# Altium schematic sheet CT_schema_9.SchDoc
size 278 x 170 mm
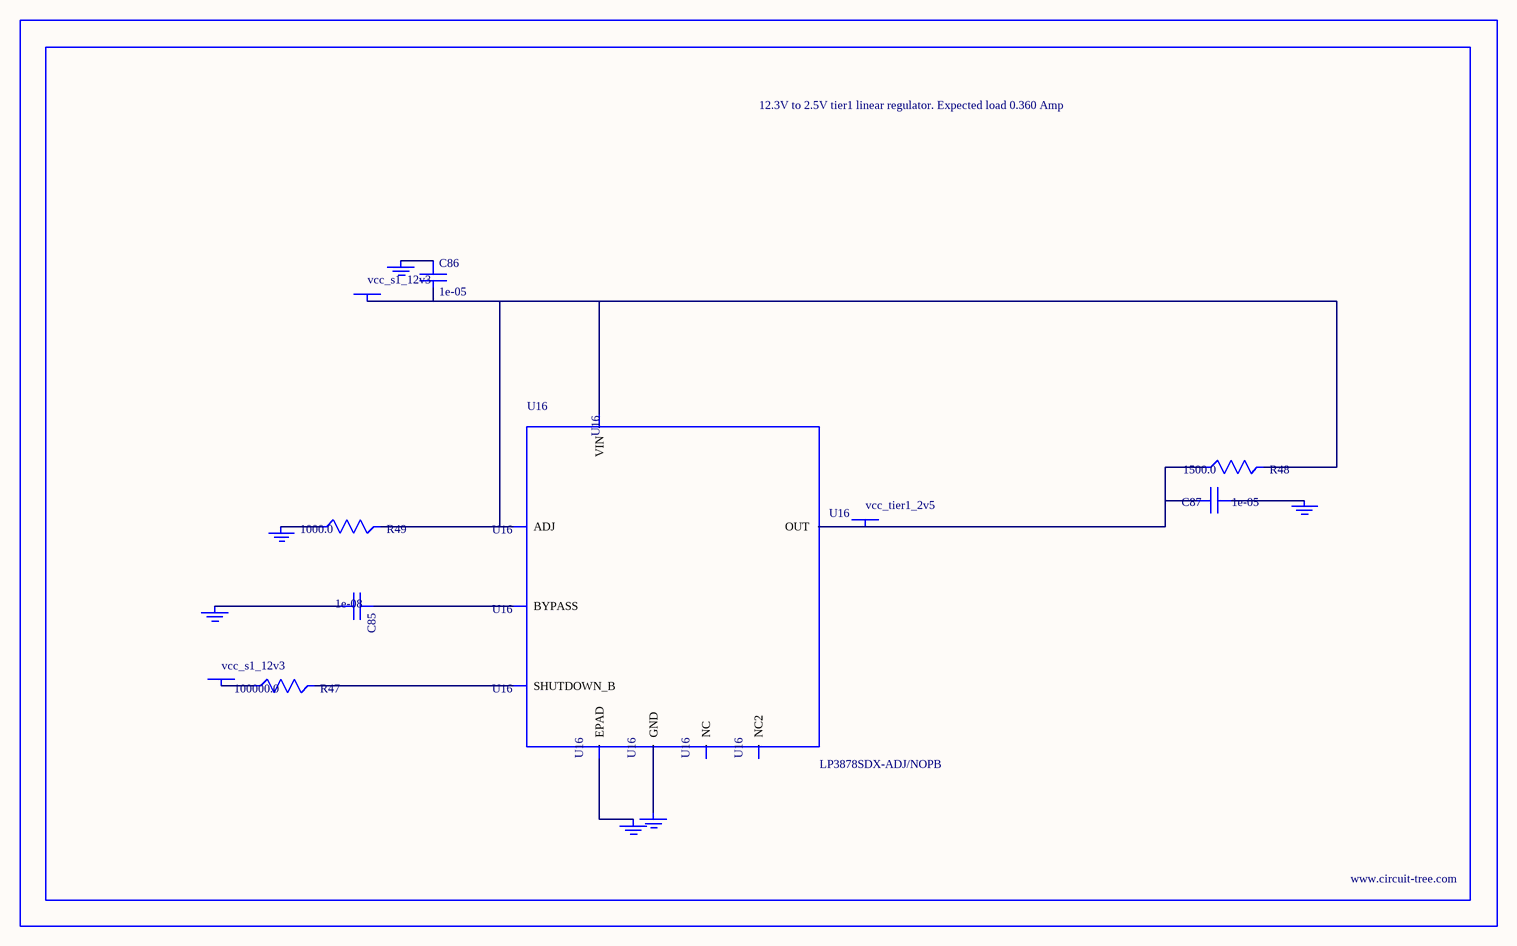
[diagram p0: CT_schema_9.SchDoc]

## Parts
BORDER8  (no value)
C85  1e-08  [C0402]
C86  1e-05  [C1210]
C87  1e-05  [C1210]
GND_INSTANCE_8_0  (no value)
GND_INSTANCE_8_1  (no value)
GND_INSTANCE_8_2  (no value)
GND_INSTANCE_8_3  (no value)
GND_INSTANCE_8_4  (no value)
GND_INSTANCE_8_5  (no value)
POWER_INSTANCE_8_0  vcc_s1_12v3
POWER_INSTANCE_8_1  vcc_s1_12v3
POWER_INSTANCE_8_2  vcc_tier1_2v5
R47  100000.0  [R0603]
R48  1500.0  [R0603]
R49  1000.0  [R0603]
U16  LP3878SDX-ADJ/NOPB  [WSON-8]

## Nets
NetC85_1: C85.1 U16.1(BYPASS)
NetC85_2: C85.2 GND_INSTANCE_8_0.0(GND)
NetC86_1: C86.1 GND_INSTANCE_8_1.0(GND)
NetC86_2: C86.2 POWER_INSTANCE_8_0.0(PWR) R48.2 R49.2 U16.4(VIN) U16.6(ADJ)
NetC87_1: C87.1 GND_INSTANCE_8_2.0(GND)
NetC87_2: C87.2 POWER_INSTANCE_8_2.0(PWR) R48.1 U16.5(OUT)
NetGND_INSTANCE_8_3_0: GND_INSTANCE_8_3.0(GND) R49.1
NetGND_INSTANCE_8_4_0: GND_INSTANCE_8_4.0(GND) U16.PAD(EPAD)
NetGND_INSTANCE_8_5_0: GND_INSTANCE_8_5.0(GND) U16.3(GND)
NetPOWER_INSTANCE_8_1_0: POWER_INSTANCE_8_1.0(PWR) R47.1
NetR47_2: R47.2 U16.8(SHUTDOWN_B)

Not connected (* = marked no-connect by the designer): U16 2(NC) 7(NC2)

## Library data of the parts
BORDER8 = BORDER_PAGE8
C85 = C0402C103K3RAC
C86 = C1210C106K5PACTU
C87 = GRM32DR61E106MA12L
GND_INSTANCE_8_0-GND_INSTANCE_8_5 = GND
POWER_INSTANCE_8_0-POWER_INSTANCE_8_2 = PWR
R47 = RC0603JR-07100KL
R48 = RC0603JR-071K5L
R49 = RC0603JR-071KL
